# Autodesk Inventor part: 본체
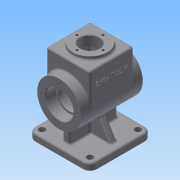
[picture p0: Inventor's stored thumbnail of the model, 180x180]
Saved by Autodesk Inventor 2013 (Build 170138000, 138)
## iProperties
Created: 2019-01
Part Number: 본체
Material: 알루미늄 6061
Document SubType Name: Modeling
Designer: mduedu
Density: 2.71 g/cm^3
Mass: 827.028 g
Surface Area: 721.983 cm^2
Volume: 305.176 cm^3
Author: mduedu
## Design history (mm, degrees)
sketch "스케치1"
  geometry: C1 r 32 at (0, 0); 1 further point
  constraints: 1 centre point, 1 coincident
  dimensions: "d0" = 64 diameter of C1
extrude "돌출1" new body sketch "스케치1" stored distance "d1" = 90; taper "d2" = 0 deg
sketch "스케치2"
  geometry: L1 (0, 32)-(50, 32); L2 (50, 32)-(50, -32); L3 (50, -32)-(0, -32); L4 (0, -32)-(0, 32); C1 r 32 at (0, 0) reference; 2 further points
  constraints: 8 end point, 2 parallel, 1 coincident, 1 horizontal, 1 midpoint, 1 perpendicular, 1 tangent
  dimensions: "d5" = 50 distance between parallel lines of L4 L2
extrude "돌출2" join sketch "스케치2" stored distance "d7" = 64; taper "d8" = 0 deg
sketch "스케치3"
  geometry: C1 r 25 at (32, 32); 1 further point
  constraints: 1 centre point, 1 coincident
  dimensions: "d9" = 50 diameter of C1
extrude "돌출3" join sketch "스케치3" distance "d10" = 5; taper "d11" = 0 deg
sketch "스케치4"
  geometry: L1 (40, 25)-(0, 25); L2 (0, 25)-(0, -25); L3 (0, -25)-(40, -25); L4 (40, -25)-(40, 25); L5 (55, -25)-(55, 25) reference; A1 r 25 centre (0, 0) between (0, 25) and (0, -25); A2 r 25 centre (0, 0) between (0, -25) and (0, 25); 2 further points
  constraints: 8 end point, 4 point on circle, 2 centre point, 2 coincident, 2 parallel, 1 horizontal, 1 midpoint, 1 perpendicular, 1 tangent
  dimensions: "d12" = 50 diameter of A1; "d13" = 15 distance between parallel lines of L4 L5
extrude "돌출4" cut sketch "스케치4" stored distance "d14" = 48; taper "d15" = 0 deg
sketch "스케치5"
  geometry: C1 r 20 at (0, 0); 1 further point
  constraints: 1 centre point, 1 coincident
  dimensions: "d16" = 40 diameter of C1
extrude "돌출5" cut sketch "스케치5" distance "d17" = 15; taper "d18" = 0 deg
sketch "스케치6"
  geometry: C1 r 17 at (0, 0); 1 further point
  constraints: 1 centre point, 1 coincident
  dimensions: "d19" = 34 diameter of C1
extrude "돌출6" cut sketch "스케치6" stored distance "d20" = 15; taper "d21" = 0 deg
fillet "모깎기1" dims "d22" = 0.3
fillet "모깎기2" dims "d23" = 3
fillet "모깎기3" dims "d24" = 3
fillet "모깎기4" dims "d25" = 3
fillet "모깎기5" dims "d26" = 3
fillet "모깎기6" dims "d27" = 3
sketch "스케치7"
  geometry: C1 r 14 at (0, 0); 1 further point
  constraints: 1 centre point, 1 coincident
  dimensions: "d28" = 28 diameter of C1
extrude "돌출7" cut sketch "스케치7" stored distance "d29" = 15; taper "d30" = 0 deg
chamfer "모따기1" distance "d31" = 1; stored, may be unused: second distance "d32" = 2, angle "d33" = 45 deg
chamfer "모따기2" distance "d34" = 1; stored, may be unused: second distance "d35" = 2, angle "d36" = 45 deg
node "작업 평면1"
sketch "스케치8"
  geometry: L1 (45, -45)-(-45, -45); L2 (-45, -45)-(-45, 45); L3 (-45, 45)-(45, 45); L4 (45, 45)-(45, -45); 3 further points
  constraints: 8 end point, 2 midpoint, 2 parallel, 1 horizontal, 1 horizontal alignment, 1 perpendicular, 1 vertical alignment
  dimensions: "d39" = 90 distance of L1.start L1.end; "d40" = 90 distance of L1.end L2.end
extrude "돌출8" join sketch "스케치8" distance "d41" = 10; taper "d42" = 0 deg
sketch "스케치9"
  geometry: L1 (-35, 5)-(35, 5); L2 (35, 5)-(35, -5); L3 (35, -5)-(-35, -5); L4 (-35, -5)-(-35, 5); 3 further points
  constraints: 8 end point, 2 midpoint, 2 parallel, 1 horizontal, 1 horizontal alignment, 1 perpendicular, 1 vertical alignment
  dimensions: "d52" = 10 distance of L1.end L2.end; "d54" = 70 distance of L1.start L1.end
extrude "돌출9" join sketch "스케치9" stored distance "d50" = 10; taper "d51" = 0 deg
sketch "스케치10"
  geometry: L1 (0, -25)-(37, -25) reference; L2 (40, -22)-(40, -14) reference; L3 (40, -14)-(54, -14) reference; L4 (54, -14)-(55, -15) reference; L5 (55, -15)-(55, -25) reference; L6 (55, -25)-(53, -25) reference; L7 (50, -28)-(50, -29) reference; L8 (47, -32)-(0, -32) reference; L9 (-31.607, -5)-(-55, -5) reference; L10 (-55, -5)-(-55, -45) reference; L11 (-55, -45)-(-65, -45) reference; L12 (-65, -45)-(-65, 45) reference; L13 (-65, 45)-(-55, 45) reference; L14 (-55, 45)-(-55, 5) reference; L15 (-55, 5)-(-31.607, 5) reference; L16 (0, 32)-(47, 32) reference; L17 (50, 29)-(50, 28) reference; L18 (53, 25)-(55, 25) reference; L19 (55, 25)-(55, 15) reference; L20 (55, 15)-(54, 14) reference; L21 (54, 14)-(40, 14) reference; L22 (40, 14)-(40, 22) reference; L23 (37, 25)-(0, 25) reference; L24 (-55, 35)-(-26.2, 18.372); A1 r 25 centre (0, 0) between (0, 25) and (0, -25) reference; A2 r 3 centre (37, -22) between (37, -25) and (40, -22) reference; A3 r 3 centre (53, -28) between (53, -25) and (50, -28) reference; A4 r 3 centre (47, -29) between (47, -32) and (50, -29) reference; A5 r 32 centre (0, 0) between (-31.607, -5) and (0, -32) reference; A6 r 32 centre (0, 0) between (0, 32) and (-31.607, 5) reference; A7 r 3 centre (47, 29) between (50, 29) and (47, 32) reference; A8 r 3 centre (53, 28) between (50, 28) and (53, 25) reference; A9 r 3 centre (37, 22) between (40, 22) and (37, 25) reference; 1 further point
  constraints: 2 end point, 1 point on circle, 1 point on line
  dimensions: "d55" = 35 vertical distance of L24.start point (0, 0); "d56" = 120 deg angle of L24 L14
feature "리브1" sketch "스케치10" dims "d57" = 1, "d58" = 10, "d59" = 0, "d60" = 0, "d61" = 1, "d62" = 1
fillet "모깎기7" dims "d63" = 3
fillet "모깎기8" dims "d64" = 3
fillet "모깎기9" dims "d65" = 10
sketch "스케치11"
  geometry: L1 (-45, 35)-(-45, -35) reference; L2 (-35, -45)-(35, -45) reference; L3 (45, -35)-(45, 35) reference; L4 (35, 45)-(-35, 45) reference; L5 (8, -29.804)-(8, -8) reference; L6 (-2, -36.732)-(2, -36.732) reference; L7 (-8, -8)-(-8, -29.804) reference; L8 (-32, -8)-(-8, -8) reference; L9 (-38, 2)-(-38, -2) reference; L10 (-8, 8)-(-32, 8) reference; L11 (-8, 29.804)-(-8, 8) reference; L12 (2, 36.732)-(-2, 36.732) reference; L13 (8, 8)-(8, 29.804) reference; L14 (32, 8)-(8, 8) reference; L15 (38, -2)-(38, 2) reference; L16 (8, -8)-(32, -8) reference; A1 r 10 centre (-35, 35) between (-35, 45) and (-45, 35) reference; A2 r 10 centre (-35, -35) between (-45, -35) and (-35, -45) reference; A3 r 10 centre (35, -35) between (35, -45) and (45, -35) reference; A4 r 10 centre (35, 35) between (45, 35) and (35, 45) reference; A5 r 6 centre (-32, -2) between (-38, -2) and (-32, -8) reference; A6 r 6 centre (-32, 2) between (-32, 8) and (-38, 2) reference; A7 r 6 centre (32, 2) between (38, 2) and (32, 8) reference; A8 r 6 centre (32, -2) between (32, -8) and (38, -2) reference; 9 further points; 4 other entities
  constraints: 4 coincident, 4 other
hole "구멍1" sketch "스케치11" at (-35, 35), (35, 35), (35, -35), (-35, -35) diameter "d66" = 9; stored, may be unused: countersink angle "d70" = 90 deg, drill point angle "d72" = 118 deg; dims "d67" = 6, "d68" = 4, "d69" = 2, "d71" = 8
fillet "모깎기10" dims "d73" = 3
sketch "스케치12"
  geometry: L1 (-3, 47)-(-3, 19.596) reference; 2 further points
  constraints: 1 other
  dimensions: "d74" = 32 distance from line of point (29, 30) L1; "d75" = 30 distance of point (29, 30) point (29, 0)
feature "엠보싱1" sketch "스케치12" dims "d76" = 0.5, "d77" = 0
sketch "스케치13"
  geometry: 4 further points
  constraints: 4 other
hole "구멍2" sketch "스케치13" at (-25, 0), (0, -25), (25, 0), (0, 25) diameter "d78" = 3.242; stored, may be unused: countersink angle "d82" = 90 deg, drill point angle "d84" = 120 deg; dims "d79" = 7, "d80" = 4, "d81" = 2, "d83" = 9
sketch "스케치14"
  geometry: 4 further points
  constraints: 4 other
hole "구멍3" sketch "스케치14" at (-25, 0), (0, -25), (25, 0), (0, 25) diameter "d85" = 3.242; stored, may be unused: countersink angle "d89" = 90 deg, drill point angle "d91" = 120 deg; dims "d86" = 7, "d87" = 4, "d88" = 2, "d90" = 9
sketch "스케치15"
  geometry: 4 further points
  constraints: 4 other
hole "구멍4" sketch "스케치15" at (0, -19), (19, 0), (0, 19), (-19, 0) diameter "d92" = 3.242; stored, may be unused: countersink angle "d96" = 90 deg, drill point angle "d98" = 120 deg; dims "d93" = 8, "d94" = 4, "d95" = 2, "d97" = 10
node "솔리드1"
mirror "대칭1"
mirror "대칭2"
node "투영된 루프1"
node "절단 모서리 투영1"
node "절단 모서리 투영2"
other parameters: "d37" = -65
